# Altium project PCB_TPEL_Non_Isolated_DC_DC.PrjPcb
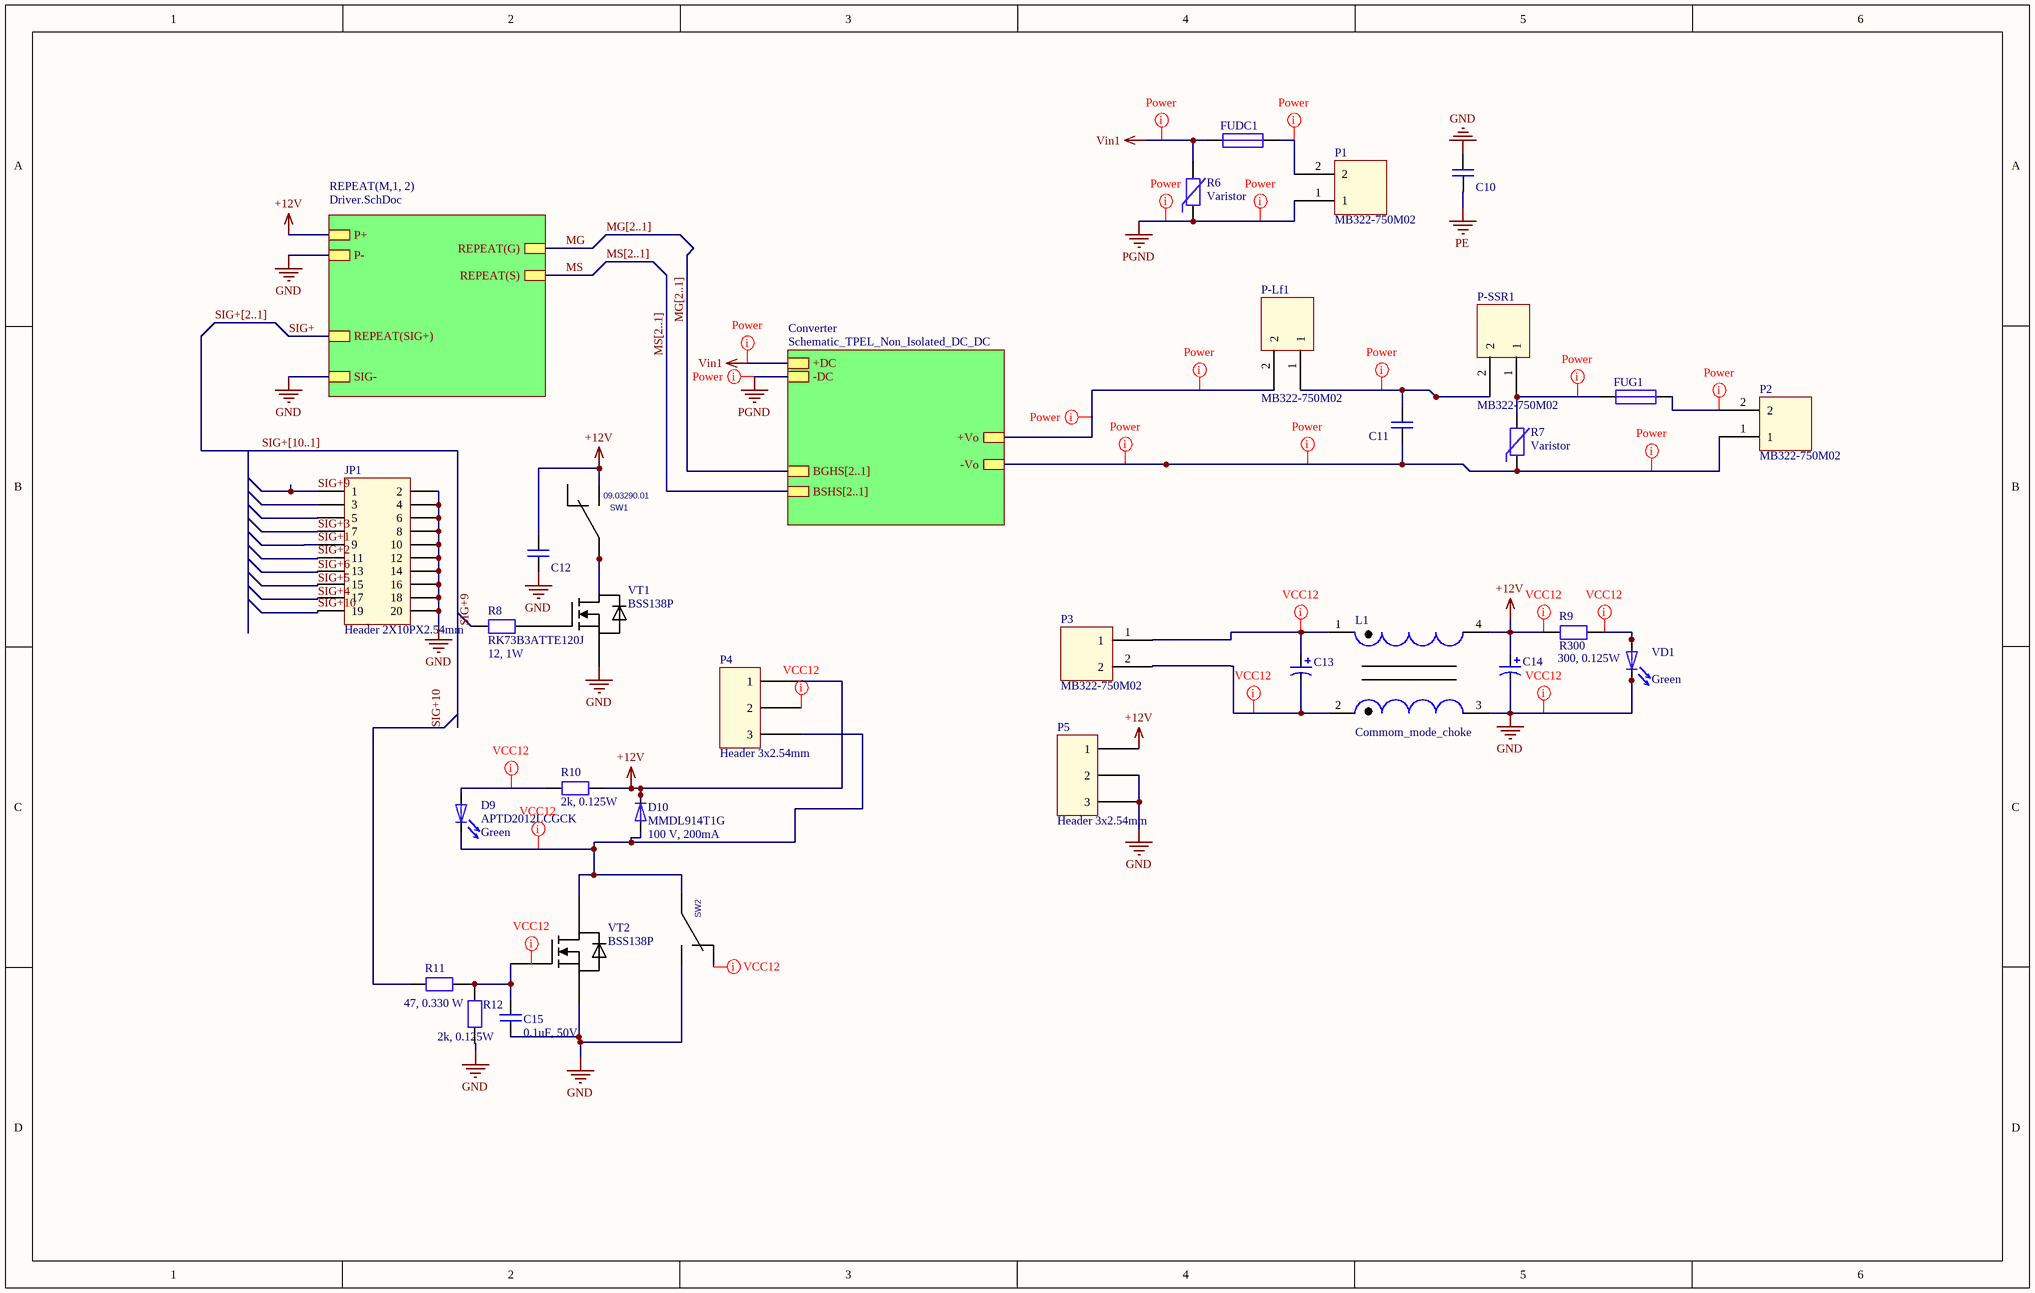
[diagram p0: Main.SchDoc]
3 sheets, 80 parts. Net scope: hierarchical (ports join the sheet entries above them; power ports are global).
Board file: PCB_TPEL_Non_Isolated_DC_DC.PcbDoc
Sheets:
  Main.SchDoc
    M1 = Driver.SchDoc
    M2 = Driver.SchDoc
    Converter = Schematic_TPEL_Non_Isolated_DC_DC.SchDoc

## Sheet Main.SchDoc
size B; SheetNumber: 1; SheetTotal: 3

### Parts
C10  Cer_large  [CAPC3227X25N]  (value not drawn)
C11  C_ceram_HV  [C_ceram_HV]  (value not drawn)
C12  Cer_large  [CAPC3227X25N]  (value not drawn)
C13  NACEW102M25V12.5X14  [Cap_pol]  (value not drawn)
C14  NACEW102M25V12.5X14  [Cap_pol]  (value not drawn)
C15  0.1uF, 50V  [C_0805]
D9  APTD2012LCGCK  value Green  [LED_SMD_0805]
D10  MMDL914T1G  value 100 V, 200mA  [SOD323F]
FUDC1  Fuse 1  [Fuse5x20mm]  (value not drawn)
FUG1  Fuse 1  [Fuse5x20mm]  (value not drawn)
JP1  Header 2X10PX2.54mm  [Header 2X10PX2.54mm]
L1  Commom_mode_choke  [Common_mode]
P1  MB322-750M02  [2_HOLES_7.5]
P2  MB322-750M02  [2_HOLES_7.5]
P3  MB322-750M02  [2_HOLES_7.5]
P4  Header 3x2.54mm  [3_HOLES]
P5  Header 3x2.54mm  [3_HOLES]
P-Lf1  MB322-750M02  [2_HOLES_7.5]
P-SSR1  MB322-750M02  [2_HOLES_7.5]
R6  Varistor  [Axial 0.2]
R7  Varistor  [Axial 0.2]
R8  RK73B3ATTE120J  value 12, 1W  [SMD_2512]
R9  R300  value 300, 0.125W  [SMD_2010]
R10  value 2k, 0.125W  [SMD_0805]  (hidden comment: 2k, 0.125W, 1%)
R11  47, 0.330 W  [SMD_0805]
R12  value 2k, 0.125W  [SMD_0805]  (hidden comment: 2k, 0.125W, 1%)
SW1  09.03290.01  [3_HOLES]
SW2  SWITCH3  [3_HOLES]  (value not drawn)
VD1  value Green  [LED_SMD_0805]  (hidden comment: APTD2012LCGCK)
VT1  BSS138P  [SOT65P210X110-3N]
VT2  BSS138P  [SOT65P210X110-3N]

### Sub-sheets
Converter = Schematic_TPEL_Non_Isolated_DC_DC: +DC, -DC, +Vo, -Vo, BSHS[2..1], BGHS[2..1]
REPEAT(M,1, 2) = Driver.SchDoc: REPEAT(G), REPEAT(S), SIG-, REPEAT(SIG+), P-, P+

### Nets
+12V: C12.1 C14.1 D10.2 L1.4 P4.1 P5.1 R9.1 R10.1 SW1.3 ; sheet REPEAT(M,1, 2)/P+
GND: C10.1 C12.2 C14.2 C15.2 JP1.2 JP1.4 JP1.6 JP1.8 JP1.10 JP1.12 JP1.14 JP1.16 JP1.18 JP1.20 L1.3 P5.2 P5.3 R12.1 SW2.3 VD1.2 VT1.3(S) VT2.3(S) ; sheet REPEAT(M,1, 2)/SIG-, sheet REPEAT(M,1, 2)/P-
PE: C10.2
PGND: C11.2 P1.1 P2.1 R6.1 R7.1 ; sheet Converter/-DC, sheet Converter/-Vo
Vin1: FUDC1.1 R6.2 ; sheet Converter/+DC
SIG+1: JP1.9
SIG+2: JP1.11
SIG+3: JP1.7
SIG+4: JP1.17
SIG+5: JP1.15
SIG+6: JP1.13
SIG+9: JP1.1 R8.1
SIG+10: JP1.19 R11.1
NetC11_1: C11.1 P-Lf1.1 P-SSR1.2
NetC13_1: C13.1 L1.1 P3.1
NetC13_2: C13.2 L1.2 P3.2
NetC15_1: C15.1 R11.2 R12.2 VT2.1(G)
NetCo_2: P-Lf1.2 ; sheet Converter/+Vo
NetD9_1: D9.1 R10.2
NetD9_2: D9.2 D10.1 P4.3 SW2.2 VT2.2(D)
NetFUDC1_2: FUDC1.2 P1.2
NetFUG1_1: FUG1.1 P-SSR1.1 R7.2
NetFUG1_2: FUG1.2 P2.2
NetR8_2: R8.2 VT1.1(G)
NetR9_2: R9.2 VD1.1
NetSW1_1: SW1.1 VT1.2(D)

Not connected (* = marked no-connect by the designer): JP1 3 5; P4 2; SW1 2; SW2 1

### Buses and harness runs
bus MG[2..1]
bus MG[2..1] = sheet Converter/BGHS[2..1]
bus MS[2..1]
bus MS[2..1] = sheet Converter/BSHS[2..1]
bus SIG+[2..1]
bus SIG+[10..1]

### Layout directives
net class +12: (no net found under the mark), +12V, GND, NetC13_1, NetC13_2, NetD9_1, NetD9_2, NetP4_2, NetR9_2, NetSW2_1
net class Power: NetC11_1, NetCo_2, NetFUDC1_2, NetFUG1_1, NetFUG1_2, PGND, Vin1

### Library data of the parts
C10 C12 = Cer_large: Order code: 1759466; Value: 22mkF; Type: 16V
C13 C14 = NACEW102M25V12.5X14: Value: 1 mF; Type: 25V; Order code: 16731346
C15 = Cap_UMF212B7104KGHT: 0.1uF, 50V, MLCC; Manufacturer: Taiyo Yuden; Order code: 963-UMF212B7104KGHT
D9 VD1 = LED_APTD2012LCGCK: Green LED, 0805; Manufacturer: Kingbright; order code: 604-APTD2012LCGCK; Type: Standard LEDs - SMD
D10 = Diode_MMDL914T1G: 100 V, 200mA, Diodes; Manufacturer: ON Semiconductor; Order code: 863-MMDL914T1G
FUDC1 FUG1 = Fuse 1: Manufacturer: Schurter; Value: Fuse 5x20; Order code: 33-173-75, 33-160-31, 33-161-63
JP1 = Header 2X10PX2.54mm: 2x10x2.54mm, Shrouded; Manufacturer: Amphenol FCI; PartNumber: 52601-S20-6LF; Order code: 649-52601-S20-6LF
L1 = Commom_mode_choke: Manufacturer: Wьrth Elektronik; Type: Common mode choke; Value: 20 mH 0.5 A; Order code: 15857854
P1-P3 P-Lf1 P-SSR1 = MB322-750M02: Value: 2 poles, 16A, 750V; Order code: 48-397-07
P4 P5 = Header_3-Pin_281695-3: 3x2.54mm, Headers & Wire Housings; Manufacturer: TE Connectivity / AMP; Order code: 571-281695-3
R6 R7 = Varistor: Manufacturer: EPCOS; Value: 615V; Order code: 60-307-55
R8 = RK73B3ATTE120J: Manufacturer: KOA; Order code: 60-205-98
R10 R12 = Res_CRCW08052K00FKEAC: 2k, 0.125W, 1%, 0805, Thick Film Resistors; Manufacturer: Vishay; Order code: 71-CRCW08052K00FKEAC
R11 = RK73H2ATTD47R0F: 47, 0.330 W, 0805, Thick Film Resistors; Manufacturer: TE Connectivity / Holsworthy; Order code: 279-CRGH0805F47R
SW1 = SW_09.03290.01: 12 VDC, Slide Switches; Manufacturer: EAO; Value: 12 VDC; Order code: 123-09.03290.01
SW2 = SWITCH3: Manufacture: EAO; Order code: 3536547
VT1 VT2 = BSS138P: Manufacturer: Nexperia; Type: APT77N60SC6; Value: 60V, 1Ohm

## Sheet Driver.SchDoc
size A; SheetNumber: 3; SheetTotal: 3
Used 2 times, as channels M1, M2. Parts and nets are listed once, with the designators drawn on the sheet.
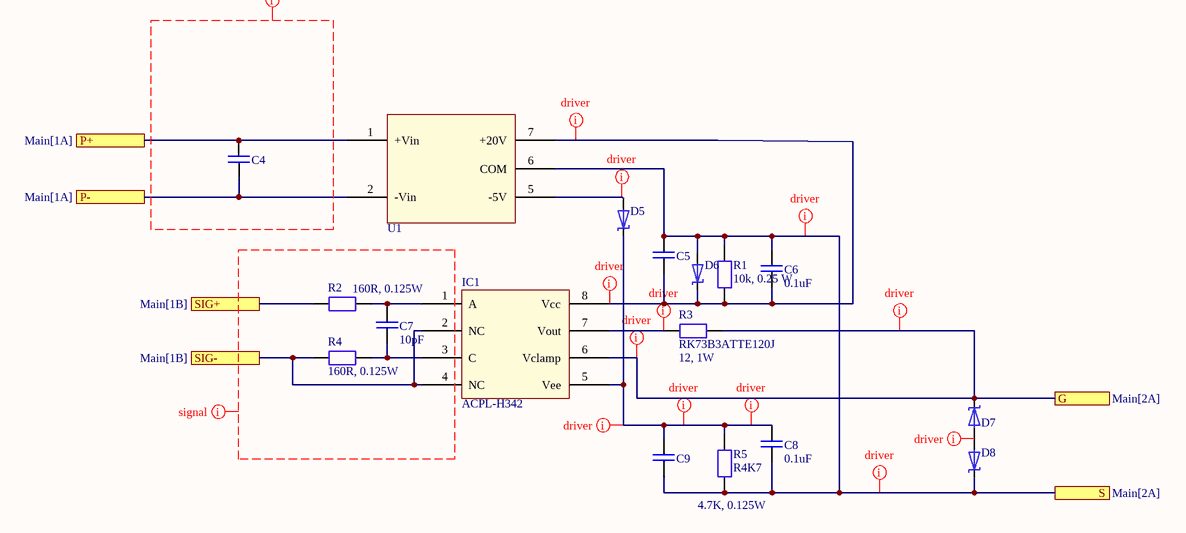
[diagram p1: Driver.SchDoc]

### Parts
C4  Cer_large  [CAPC3227X25N]  (value not drawn)
C5  Cer_large  [CAPC3227X25N]  (value not drawn)
C6  value 0.1uF  [C_0805]  (hidden comment: C0805C104K5RAC)
C7  value 10pF  [C_0805]  (hidden comment: C0805C100J1GAC)
C8  value 0.1uF  [C_0805]  (hidden comment: C0805C104K5RAC)
C9  Cer_large  [CAPC3227X25N]  (value not drawn)
D5  Zener_1.8V  [SOD123]  (value not drawn)
D6  DZ2J220M0L  [SOD323F]  (value not drawn)
D7  MMSZ4678T1G  [CAPM3216X18N]  (value not drawn)
D8  MMSZ4678T1G  [CAPM3216X18N]  (value not drawn)
IC1  ACPL-H342  [SOIC127P970X330-8N]
R1  value 10k, 0.25 W  [SMD_1206]  (hidden comment: RK73H2BTTD1002F)
R2  value 160R, 0.125W  [SMD_0805]  (hidden comment: RK73H2ATTD1600F)
R3  RK73B3ATTE120J  value 12, 1W  [SMD_2512]
R4  value 160R, 0.125W  [SMD_0805]  (hidden comment: RK73H2ATTD1600F)
R5  R4K7  value 4.7K, 0.125W  [smd_0603]
U1  MGJ2D242005SC  [MGJ2]  (value not drawn)

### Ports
G (see Main[2A]), P+ (see Main[1A]), P- (see Main[1A]), S (see Main[2A]), SIG+ (see Main[1B]), SIG- (see Main[1B])

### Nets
G: D7.1 IC1.6(Vclamp) R3.2 ; port G
P+: C4.1 U1.1(+Vin) ; port P+
P-: C4.2 U1.2(-Vin) ; port P-
S: C5.1 C6.1 C8.2 C9.2 D6.1 D8.1 R1.2 R5.1 U1.6(COM) ; port S
SIG+: R2.1 ; port SIG+
SIG-: IC1.2(NC) IC1.4(NC) R4.1 ; port SIG-
NetC5_2: C5.2 C6.2 D6.2 IC1.8(Vcc) R1.1 U1.7(+20V)
NetC7_1: C7.1 IC1.1(A) R2.2
NetC7_2: C7.2 IC1.3(C) R4.2
NetC8_1: C8.1 C9.1 D5.2 IC1.5(Vee) R5.2
NetD5_1: D5.1 U1.5(-5V)
NetD7_2: D7.2 D8.2
NetIC1_7: IC1.7(Vout) R3.1

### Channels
M1: designators end in _M1; ports G=G1 P+=+12V P-=GND S=MS1 SIG+=SIG+1 SIG-=GND
M2: designators end in _M2; ports G=G2 P+=+12V P-=GND S=MS2 SIG+=SIG+2 SIG-=GND

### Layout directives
net class Driver: G1, MS1, NetC5_M1_2, NetC8_M1_1, NetD5_M1_1, NetD7_M1_2, NetIC1_M1_7
net class Signal: (no net found under the mark)

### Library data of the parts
C4 C5 C9 = Cer_large: as C10 on sheet Main
C6 C8 = C0805C104K5RAC: 0.1u, 50V; Manufacturer: Kemet; Order code: 6576631
C7 = C0805C100J1GAC: 10p, 100V; Manufacturer: Kemet; Order code: 6576805
D5 = Zener_1.8V: Zener diode; Type: 0.5W; Value: 1.8V; Order code: 1459115
D6 = DZ2J220M0L: Type: Zener diode; Value: 22V, 200mW; Order code: 2285315
D7 D8 = Zener_MMSZ5233BT1G: 6V, 500mW, Zener Diodes; Manufacturer: ON Semiconductor; Order code: 863-MMSZ5233BT1G
IC1 = ACPL-H342: Manufacturer: Avago; Order code: 1833408; Value: 2,5 A, 12-30V
R1 = RK73H2BTTD1002F: 10k, 0.25 W; Manufacturer: KOA; Order code: 6019731
R2 R4 = RK73H2ATTD1600F: 160R, 0.125W; Manufacturer: KOA; Order code: 60-173-05
R3 = RK73B3ATTE120J: Manufacturer: KOA; Order code: 60-205-98
R5 = R4K7: Order code: 9332154
U1 = MGJ2D242005SC: Value: 2W; Order code: 2420071

## Sheet Schematic_TPEL_Non_Isolated_DC_DC.SchDoc
size A; SheetNumber: 2; SheetTotal: 3
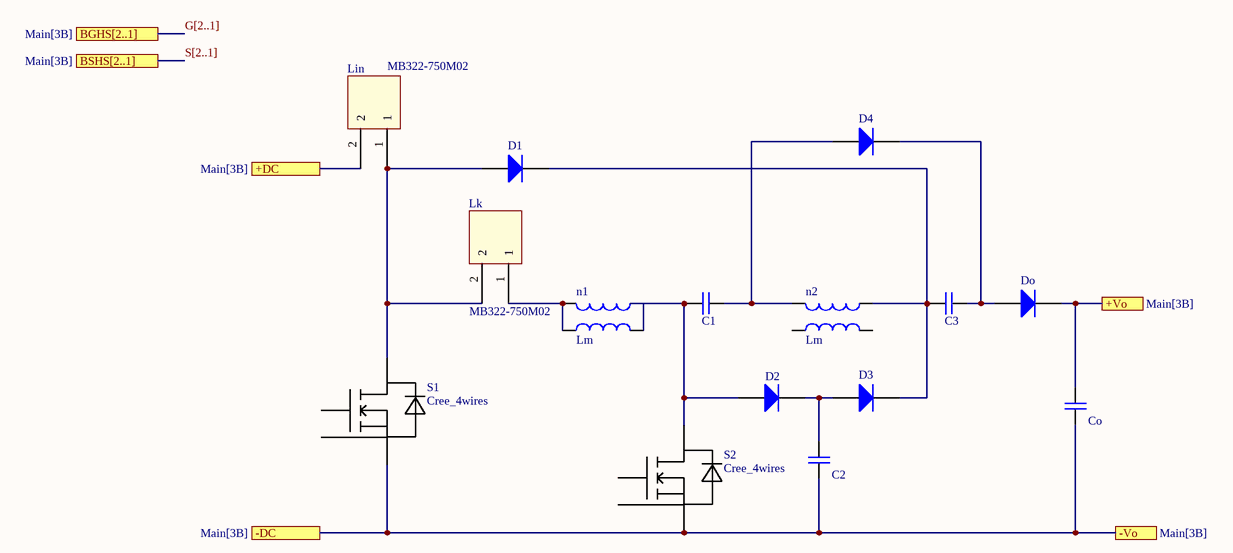
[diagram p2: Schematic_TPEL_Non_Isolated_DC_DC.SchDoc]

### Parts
C1  C_ceram_HV  [CAP_250V]  (value not drawn)
C2  C_ceram_HV  [CAP_250V]  (value not drawn)
C3  C_ceram_HV  [CAP_250V]  (value not drawn)
Co  C_ceram_HV  [CAP_250V]  (value not drawn)
D1  Diode  (value not drawn)
D2  Diode  (value not drawn)
D3  Diode  (value not drawn)
D4  Diode  (value not drawn)
Do  Diode  (value not drawn)
Lin  MB322-750M02  [2_HOLES_7.5]
Lk  MB322-750M02  [2_HOLES_7.5]
n1  L1: Lm  (hidden comment: Pair of Coupled Inductors)
n2  L1: Lm  (hidden comment: Pair of Coupled Inductors)
S1  Cree_4wires  [VT4_SicMosfet]
S2  Cree_4wires  [VT4_SicMosfet]

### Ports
+DC (see Main[3B]), +Vo (see Main[3B]), -DC (see Main[3B]), -Vo (see Main[3B]), BGHS[2..1] (see Main[3B]), BSHS[2..1] (see Main[3B])

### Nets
PGND: C2.1 Co.1 S1.2(S) S2.2(S) ; port -DC, port -Vo
Vin1: Lin.2 ; port +DC
NetC1_1: C1.1 D4.1(A) n2.1
NetC1_2: C1.2 D2.1(A) n1.2 n1.4 S2.1(D)
NetC2_2: C2.2 D2.2(K) D3.1(A)
NetC3_1: C3.1 D4.2(K) Do.1(A)
NetC3_2: C3.2 D1.2(K) D3.2(K) n2.2
NetCo_2: Co.2 Do.2(K) ; port +Vo
NetD1_1: D1.1(A) Lin.1 Lk.2 S1.1(D)
NetLk_1: Lk.1 n1.1 n1.3

Not connected (* = marked no-connect by the designer): n2 3 4; S1 3(SG) 4(G); S2 3(SG) 4(G)

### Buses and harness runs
bus G[2..1] = port BGHS[2..1]
bus S[2..1] = port BSHS[2..1]

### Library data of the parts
D1-D4 Do = Diode: AF: 1; BV: 0; BV_MAX: 1e99; EG: 1.11; FC: 0.5; IBV: 0.001; ISR: 1e-14; MJSW: 0.33; NTUN: 30; TNOM: 27; XTI: 3; SimulationGenericComponent: True
Lin Lk = MB322-750M02: as P1 on sheet Main
n1 n2 = Coupled Inductors: SimulationGenericComponent: True

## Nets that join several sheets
+12V: Main (9 pins), M1 (C4_M1.1 U1_M1.1), M2 (C4_M2.1 U1_M2.1)
GND: Main (22 pins), M1 (5 pins), M2 (5 pins)
PGND: Main (5 pins), Schematic_TPEL_Non_Isolated_DC_DC (C2.1 Co.1 S1.2 S2.2)
Vin1: Main (FUDC1.1 R6.2), Schematic_TPEL_Non_Isolated_DC_DC (Lin.2)
NetCo_2: Main (P-Lf1.2), Schematic_TPEL_Non_Isolated_DC_DC (Co.2 Do.2)
SIG+1: Main (JP1.9), M1 (R2_M1.1)
SIG+2: Main (JP1.11), M2 (R2_M2.1)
